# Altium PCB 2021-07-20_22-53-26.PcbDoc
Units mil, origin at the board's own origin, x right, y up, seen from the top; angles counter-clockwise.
Board outline 1080 x 1450 mil, 4 copper layers (Top Layer, MidLayer1, MidLayer2, Bottom Layer); 15 components, 6 nets, 31 pads, 21 vias.
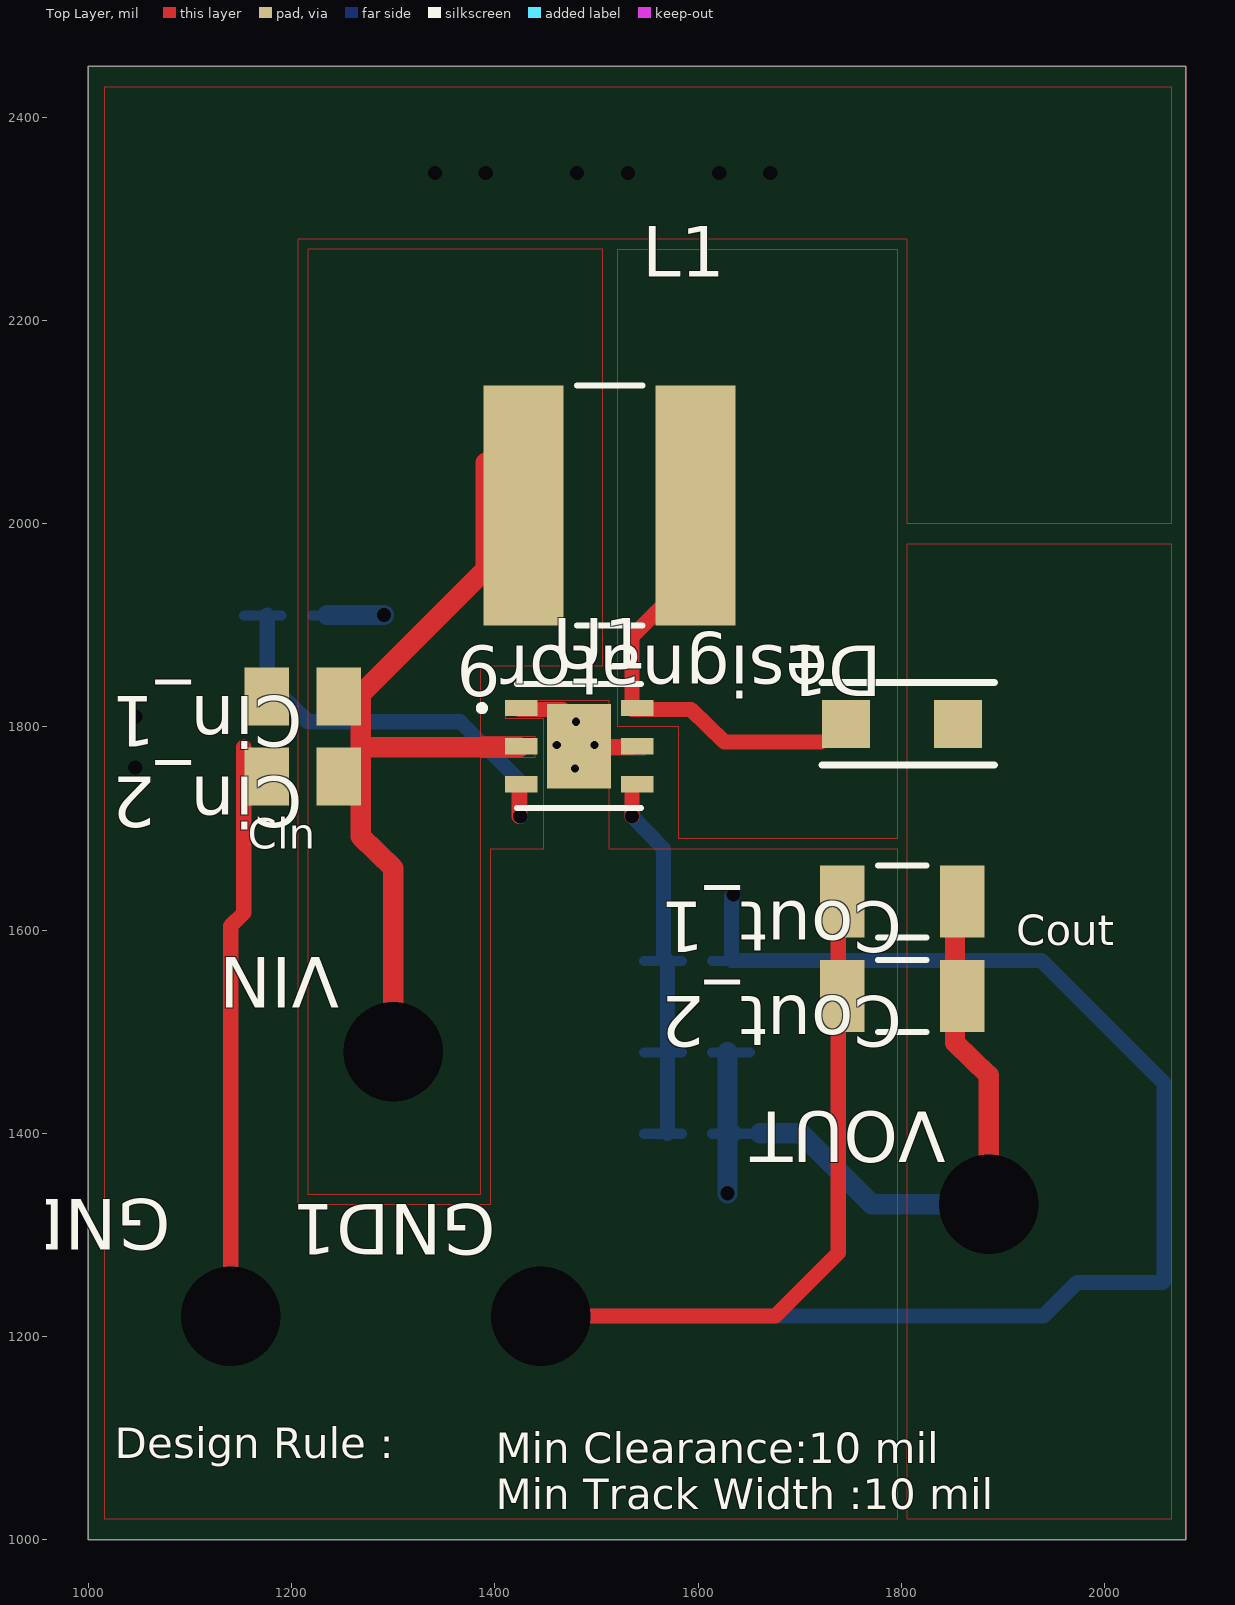
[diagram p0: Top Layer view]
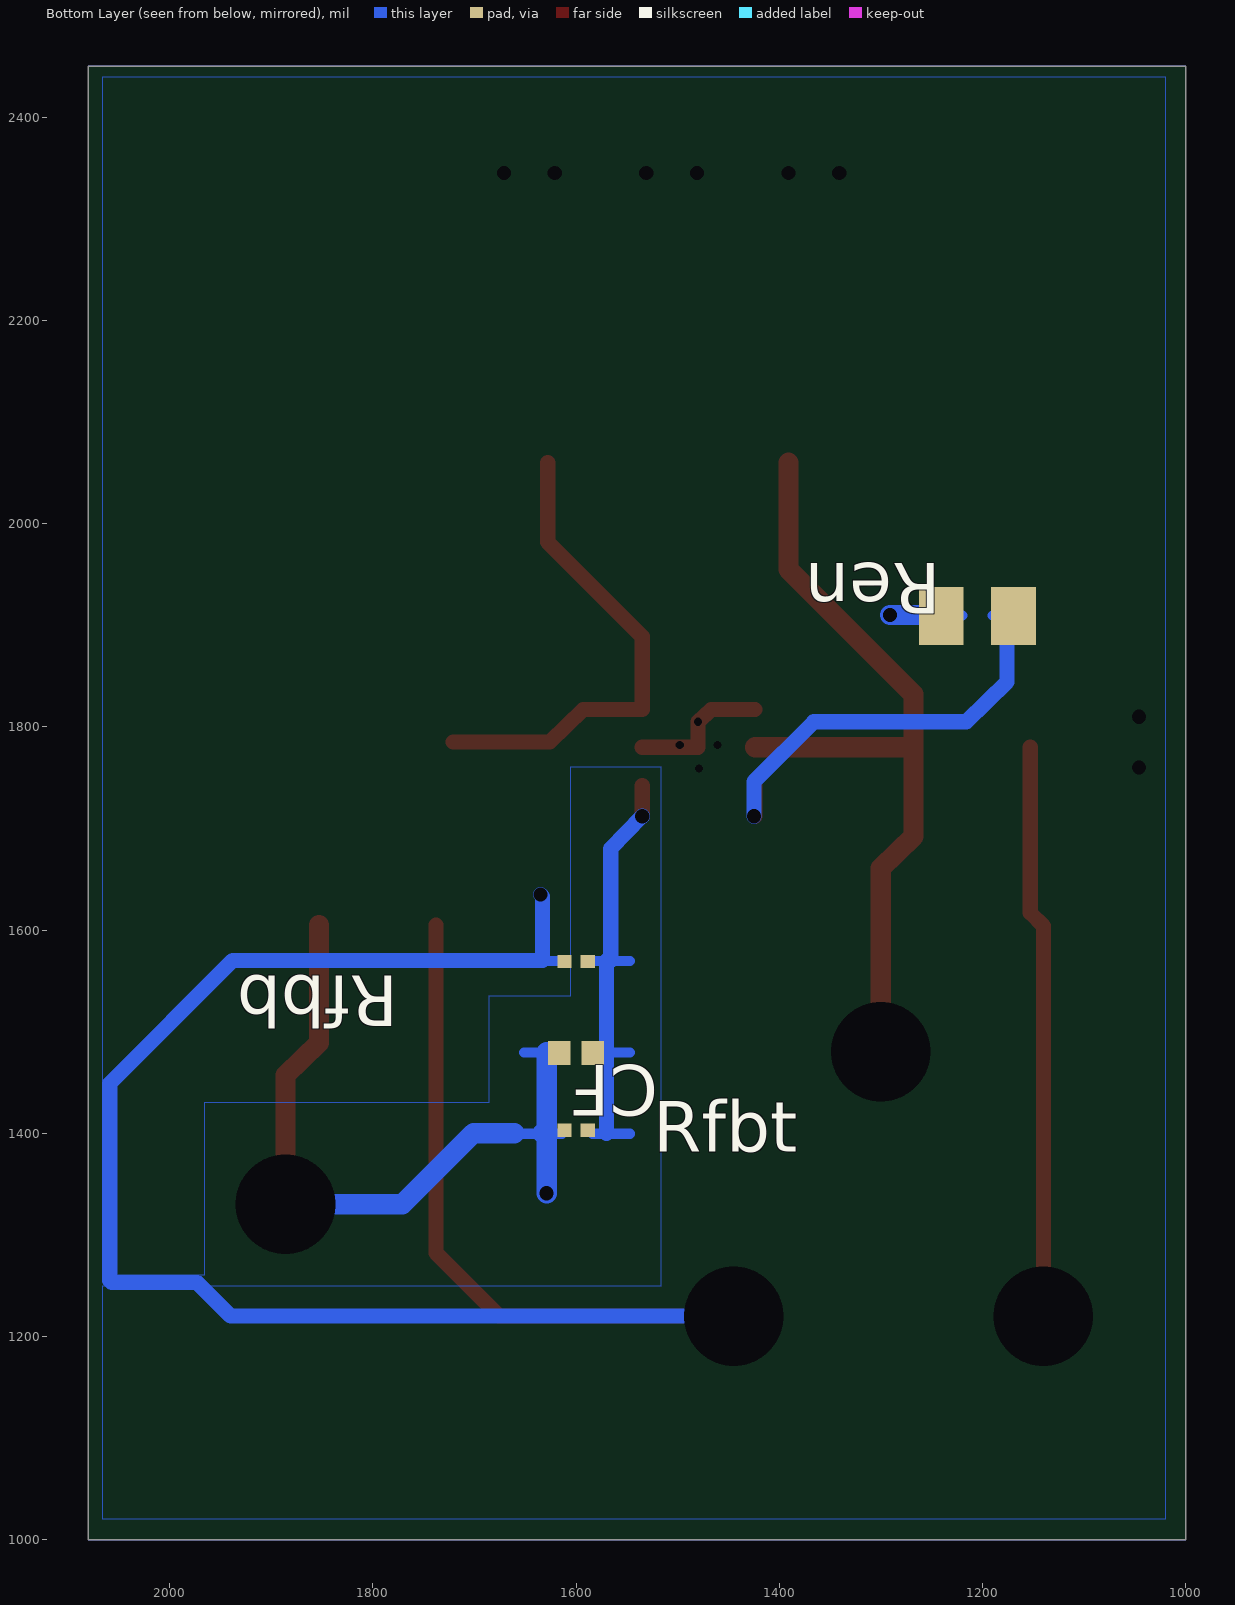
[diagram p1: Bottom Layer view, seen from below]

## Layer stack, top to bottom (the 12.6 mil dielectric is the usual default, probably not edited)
Top Layer: signal copper 1.4
Dielectric: core 12.6, FR-4, Dk 4.8
MidLayer1: signal copper 1.4
Dielectric: prepreg 12.6, FR-4, Dk 4.8
MidLayer2: signal copper 1.4
Dielectric: core 12.6, FR-4, Dk 4.8
Bottom Layer: signal copper 1.4

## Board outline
1000,1000 2080,1000 2080,2450 1000,2450

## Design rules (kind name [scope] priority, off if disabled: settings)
PlaneConnect [All] p0: scope1count=1 scope1_0_kind=Board scope1_0_value=Board scope2count=1 scope2_0_kind=Board scope2_0_value=Board commentlength=0 planeconnectstyle=Direct reliefexpansion=20 reliefentries=4 reliefconductorwidth=10 reliefairgap=10
PlaneConnect [All] p1: planeconnectstyle=Direct reliefexpansion=20 reliefentries=4 reliefconductorwidth=10 reliefairgap=10
PolygonConnect [All] p0: scope1count=1 scope1_0_kind=Board scope1_0_value=Board scope2count=1 scope2_0_kind=Board scope2_0_value=Board commentlength=0 connectstyle=Direct reliefconductorwidth=10 reliefentries=4 polygonreliefangle="90 Angle"
PolygonConnect [All] p1: connectstyle=Direct reliefconductorwidth=10 reliefentries=4 polygonreliefangle="90 Angle"

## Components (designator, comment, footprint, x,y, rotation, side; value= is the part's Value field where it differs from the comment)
CF "" 0402 1600,1479 r180 bottom
Cin_1 "" 0805#1 1211,1830 r180 top
Cin_2 "" 0805#1 1211,1751 r180 top
Cout_1 "" 1206_190 1801,1628 r180 top
Cout_2 "" 1206_190 1801,1535 r180 top
D1 "" SOD-123F 1801,1803 r180 top
GND "" TP-1502 1139,1219 r180 top
GND1 "" TP-1502 1444,1219 r180 top
L1 "" SRN6045 1513,2018 r0 top
Ren "" 0805#2 1205,1909 r180 bottom
Rfbb "" 0201 1600,1569 r180 bottom
Rfbt "" 0201 1600,1403 r0 bottom
U1 "" SDE06A 1483,1781 r0 top
VIN "" TP-1502 1299,1479 r180 top
VOUT "" TP-1502 1885,1328 r180 top

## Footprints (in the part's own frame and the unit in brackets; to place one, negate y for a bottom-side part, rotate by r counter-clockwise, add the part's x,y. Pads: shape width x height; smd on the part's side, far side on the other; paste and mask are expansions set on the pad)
0201 [mil]
  rect 14x13 smd: 1(11.5,0) 2(-11.5,0)
0402 [mil]
  rect 22x24 smd: 1(16.5,0) 2(-16.5,0)
0805#1 [mil]
  rect 44x57 smd: 1(-35.5,0) 2(35.5,0)
0805#2 [mil]
  rect 44x57 smd: 1(35.5,0) 2(-35.5,0)
1206_190 [mil]
  rect 44x71 smd: 1(-59,0) 2(59,0)
  silkscreen extent -24,-36 24,36
SDE06A [mil]
  rect 32x16 smd: 1(-57,37.4) 2(-57,0) 3(-57,-37.4) 4(57,-37.4) 5(57,0) 6(57,37.4)
  rect 63x83 smd: 7(0,0)
  silkscreen extent -99,-61 61,61
SOD-123F [mm]
  rect 1.2x1.2 smd: 1(-1.4,0) 2(1.4,0)
  silkscreen extent -2.31,-1.03 2.01,1.03
SRN6045 [mm]
  rect 2x6 smd: 1(-2.15,0) 2(2.15,0)
  silkscreen extent -0.82,-3 0.82,3
TP-1502 [mil]
  round 65 / inner round 0 / far side round 65 hole 32: 1(0,0)

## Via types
v1: diameter 0, hole 14, Top Layer to Bottom Layer, 13 vias
v2: diameter 0, hole 8, Top Layer to Bottom Layer, 4 vias
v3: diameter 0, hole 98, Top Layer to Bottom Layer, 4 vias

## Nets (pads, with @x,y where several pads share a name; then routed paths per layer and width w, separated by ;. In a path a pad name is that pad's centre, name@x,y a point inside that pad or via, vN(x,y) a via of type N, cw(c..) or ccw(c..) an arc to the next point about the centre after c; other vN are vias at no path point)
0: Cin_1.2 Cin_2.2 Cout_1.2 Cout_2.2 GND1.1 GND.1 Rfbb.2 U1.1 U1.5 U1.7 | length 2704.2
  Top Layer w15: v3(1140,1220) 1140,1604 1153,1617 1153,1780 ; U1.1@1424,1817 1467,1817 v2(1480,1805) 1480,1780 U1.5@1535,1780 ; 1490,1220 1676,1220 1738,1282 Cout_1.2@1738,1605
  Bottom Layer w10: Rfbb.2@1614,1569.5 1651,1569.5
  Bottom Layer w15: v3(1445,1220) 1940,1220 1973,1253 2057,1253 2059,1255 2059,1449 1938,1570 1633,1570 1633,1633 v1(1635,1635)
  other v1: 1046,1760 1046,1810 1341,2345 1391,2345 1481,2345 1531,2345 1621,2345 1671,2345
  other v2: 1479,1759 1461,1782 1498,1782
1: Ren.1 U1.3 | length 456.3
  Top Layer w15: 1424,1712 U1.3@1424,1742
  Bottom Layer w10: Ren.1@1153,1909.5 Ren.1@1190,1909.5
  Bottom Layer w15: Ren.1@1176,1910 1176,1844 1216,1805 1366,1805 1425,1746 v1(1425,1712)
3: CF.1 Rfbb.1 Rfbt.2 U1.4 | length 465.6
  Top Layer w15: v1(1535,1712) U1.4@1535,1742
  Bottom Layer w10: 1547,1399.5 Rfbt.2@1584,1399.5 ; 1547,1479.5 CF.1@1584,1479.5 ; 1547,1569.5 Rfbb.1@1584,1569.5
  Bottom Layer w15: v1(1535,1712) 1566,1680 1566,1570 ; 1570,1400 1570,1570
5: CF.2 Cout_1.1 Cout_2.1 D1.1 Rfbt.1 VOUT.1 | length 760
  Top Layer w20: Cout_1.1@1853,1605 1853,1489 1886,1457 v3(1886,1330)
  Bottom Layer w10: Rfbt.1@1614,1399.5 1651,1399.5 ; CF.2@1614,1479.5 1651,1479.5
  Bottom Layer w20: v1(1629,1341) 1629,1400 ; 1629,1480 1629,1400 ; 1633,1400 1629,1400 ; 1661,1400 1701,1400 1771,1330 v3(1886,1330)
6: Cin_1.1 Cin_2.1 L1.1 Ren.2 U1.2 VIN.1 | length 893.5
  Top Layer w20: v3(1300,1480) 1300,1661 1268,1692 1268,1780 ; L1.1@1391,2060 1391,1955 1268,1832 1268,1780 ; U1.2@1424,1780 1268,1780
  Bottom Layer w10: Ren.2@1220,1909.5 Ren.2@1257,1909.5
  Bottom Layer w20: Ren.2@1235,1910 v1(1291,1910)
7: D1.2 L1.2 U1.6 | length 480.5
  Top Layer w15: L1.2@1628,2060 1628,1982 1535,1889 1535,1817 1593,1817 1626,1785 1721,1785

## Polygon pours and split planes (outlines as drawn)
5 on Top Layer " " (solid, pour order 0): 2066,1980 2066,1020 1806,1020 1806,1980
7 on Top Layer " " (solid, pour order 1): 1521,1800 1521,2270 1796,2270 1796,1690 1581,1690 1581,1800
6 on Top Layer " " (solid, pour order 2): 1216,1340 1386,1340 1386,1770 1440,1770 1440,1790 1386,1790 1386,1860 1506,1860 1506,2270 1216,2270
0 on Top Layer " " (solid, pour order 4): 1512,1826 1512,1788 1548,1788 1548,1772 1512,1772 1512,1680 1796,1680 1796,1020 1016,1020 1016,2430 2066,2430 2066,2000 1806,2000 1806,2280 1206,2280 1206,1330 1396,1330 1396,1680 1448,1680 1448,1808 1411,1808 1411,1826
0 on Bottom Layer " " (solid, pour order 3): 1020,1020 2066,1020 2066,1250 1516,1250 1516,1760 1606,1760 1606,1535 1686,1535 1686,1430 1966,1430 1966,1260 2066,1260 2066,2440 1020,2440

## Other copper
Multi-Layer:
  the board outline again, w1

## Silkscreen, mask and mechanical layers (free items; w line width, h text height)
Top Overlay:
  text "Cin" at 1157,1680 h30
  text "Cout" at 1913,1585 h30
  text "Design Rule :" at 1026,1080 h30
  text "Min Clearance:10 mil" at 1401,1075 h30
  text "Min Track Width :10 mil" at 1401,1030 h30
